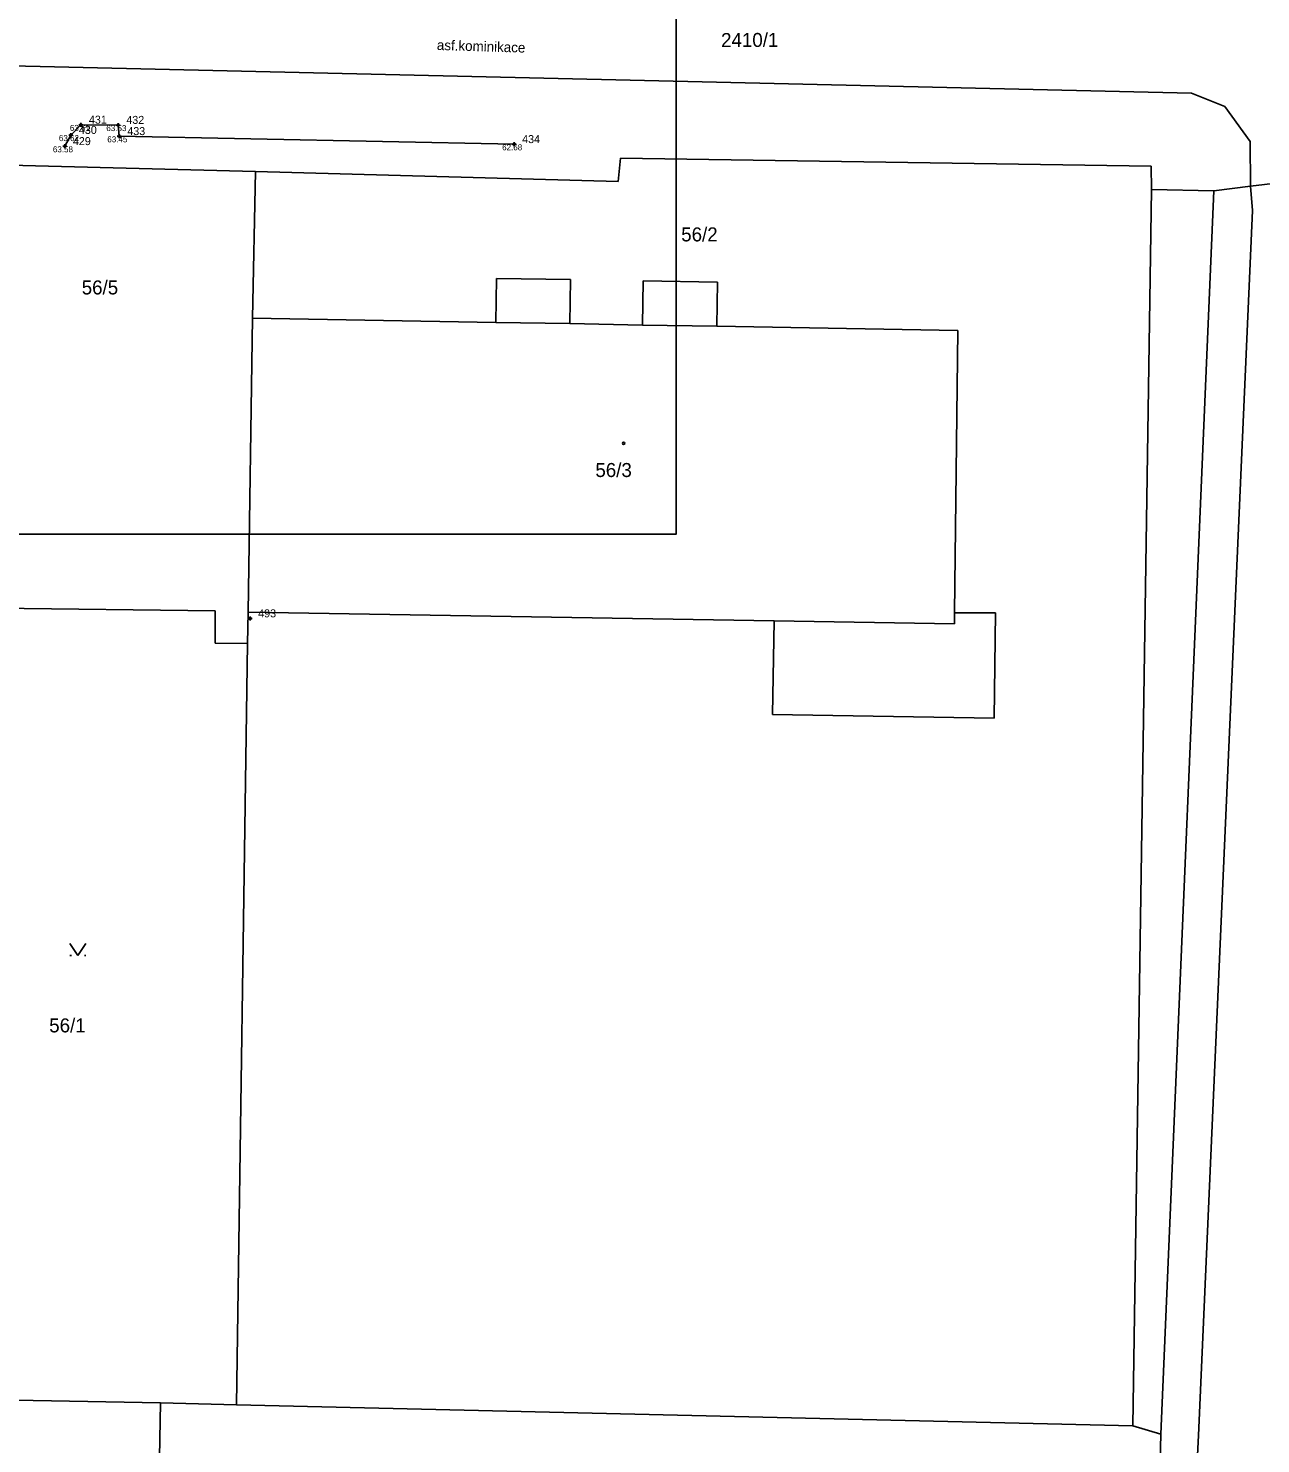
# Model space of a CAD drawing. Extents: x -454285 to -453563, y -1108687 to -1108249.
# Drawn here: x -453822.5 to -453760.9, y -1108547.2 to -1108476.5 of the extents above; entities that cross this region are included whole.
import ezdxf

# ---------------------------------------------------------------- set-up
doc = ezdxf.new("R2010")
doc.units = 0
for name, color, linetype in [('1', 7, 'Continuous'), ('14', 7, 'Continuous'), ('15', 7, 'Continuous'), ('16', 7, 'Continuous'), ('2', 7, 'Continuous'), ('23', 7, 'Continuous'), ('25', 7, 'Continuous'), ('BODY_T1_2018', 7, 'Continuous'), ('CISLA_T1_2018', 7, 'Continuous'), ('okraj asf.komunikace', 7, 'Continuous'), ('rámy', 7, 'Continuous'), ('T', 7, 'Continuous'), ('VYSKY_T1_2018', 7, 'Continuous')]:
    doc.layers.add(name, color=color, linetype=linetype)

# ---------------------------------------------------------------- blocks, each defined once
blk = doc.blocks.new('Z402')
for start, end in [(0, 180), (180, 0)]:
    blk.add_arc((0, 0), 0.15, start, end)
blk = doc.blocks.new('Z3140')
for p, q in [((-1, 1.5), (0, 0)), ((-1, 0), (-0.8, 0)), ((0, 0), (1, 1.5)), ((0.8, 0), (1, 0))]:
    blk.add_line(p, q)
blk = doc.blocks.new('POINT_DISPLAY')
for p, q in [((-0.1, 0), (0.1, 0)), ((0, -0.1), (0, 0.1))]:
    blk.add_line(p, q)
blk.add_circle((0, 0), 0.05)
blk = doc.blocks.new('t1_2018')
at = {"layer": 'BODY_T1_2018'}
for p in [(-453820.39, -1108481.82), (-453819.89, -1108481.31), (-453818.02, -1108481.32), (-453817.97, -1108481.88), (-453820.69, -1108482.38), (-453798.24, -1108482.28), (-453811.43, -1108505.98)]:
    blk.add_blockref('POINT_DISPLAY', p, dxfattribs=at)
at = {"layer": 'CISLA_T1_2018'}
for s, p in [('431', (-453819.49, -1108481.25)), ('432', (-453817.62, -1108481.26)), ('430', (-453819.99, -1108481.76)), ('433', (-453817.57, -1108481.82)), ('429', (-453820.29, -1108482.32)), ('434', (-453797.84, -1108482.22)), ('493', (-453811.03, -1108505.92))]:
    blk.add_text(s, height=0.4, dxfattribs=at).set_placement(p)
at = {"layer": 'VYSKY_T1_2018'}
for s, p in [('63.61', (-453820.44, -1108481.61)), ('63.53', (-453818.62, -1108481.62)), ('63.58', (-453821.29, -1108482.68)), ('63.62', (-453820.99, -1108482.12)), ('63.45', (-453818.57, -1108482.18)), ('62.68', (-453798.84, -1108482.58))]:
    blk.add_text(s, height=0.3, dxfattribs=at).set_placement(p)

msp = doc.modelspace()

# ---------------------------------------------------------------- linework, layer by layer
at = {"layer": '1'}
for p, q in [((-453793.047, -1108484.141), (-453792.927, -1108482.971)), ((-453792.927, -1108482.971), (-453766.407, -1108483.371)), ((-453811.157, -1108483.631), (-453826.077, -1108483.251)), ((-453811.157, -1108483.631), (-453811.317, -1108490.961)), ((-453811.157, -1108483.631), (-453793.047, -1108484.141)), ((-453766.407, -1108483.371), (-453766.387, -1108484.531)), ((-453766.387, -1108484.531), (-453763.277, -1108484.601)), ((-453765.927, -1108546.741), (-453763.277, -1108484.601)), ((-453763.277, -1108484.601), (-453761.447, -1108484.371)), ((-453761.447, -1108484.371), (-453757.687, -1108483.911)), ((-453799.117, -1108488.981), (-453799.157, -1108491.181)), ((-453799.117, -1108488.981), (-453795.417, -1108489.041)), ((-453795.417, -1108489.041), (-453795.457, -1108491.241)), ((-453791.827, -1108491.311), (-453791.797, -1108489.111)), ((-453791.797, -1108489.111), (-453788.077, -1108489.171)), ((-453788.077, -1108489.171), (-453788.107, -1108491.371)), ((-453811.537, -1108505.661), (-453811.317, -1108490.961)), ((-453811.317, -1108490.961), (-453799.157, -1108491.181)), ((-453795.457, -1108491.241), (-453791.827, -1108491.311)), ((-453788.107, -1108491.371), (-453776.067, -1108491.581)), ((-453776.237, -1108505.691), (-453776.067, -1108491.581)), ((-453813.187, -1108505.601), (-453826.417, -1108505.431)), ((-453813.187, -1108505.601), (-453813.177, -1108507.211)), ((-453811.537, -1108505.661), (-453811.557, -1108507.221)), ((-453811.537, -1108505.661), (-453785.237, -1108506.091)), ((-453774.187, -1108505.691), (-453776.237, -1108505.691)), ((-453774.247, -1108510.961), (-453774.187, -1108505.691)), ((-453785.237, -1108506.091), (-453785.327, -1108510.781)), ((-453813.177, -1108507.211), (-453811.557, -1108507.221)), ((-453811.557, -1108507.221), (-453812.107, -1108545.271)), ((-453785.327, -1108510.781), (-453774.247, -1108510.961)), ((-453832.427, -1108544.861), (-453815.917, -1108545.181)), ((-453816.177, -1108561.151), (-453815.917, -1108545.181)), ((-453815.917, -1108545.181), (-453812.107, -1108545.271)), ((-453812.107, -1108545.271), (-453767.317, -1108546.321)), ((-453765.927, -1108546.741), (-453767.887, -1108627.791)), ((-453767.317, -1108546.321), (-453765.927, -1108546.741))]:
    msp.add_line(p, q, dxfattribs=at)
at = {"layer": '2'}
for p, q in [((-453827.527, -1108478.261), (-453764.397, -1108479.731)), ((-453764.397, -1108479.731), (-453762.717, -1108480.391)), ((-453762.717, -1108480.391), (-453761.457, -1108482.141)), ((-453761.457, -1108482.141), (-453761.447, -1108484.371)), ((-453766.387, -1108484.531), (-453767.317, -1108546.321)), ((-453761.447, -1108484.371), (-453761.347, -1108485.581)), ((-453761.347, -1108485.581), (-453764.047, -1108546.801)), ((-453799.157, -1108491.181), (-453795.457, -1108491.241)), ((-453791.827, -1108491.311), (-453788.107, -1108491.371)), ((-453776.237, -1108505.691), (-453776.237, -1108506.241)), ((-453785.237, -1108506.091), (-453776.237, -1108506.241)), ((-453764.107, -1108548.121), (-453764.047, -1108546.801))]:
    msp.add_line(p, q, dxfattribs=at)
at = {"layer": 'okraj asf.komunikace'}
msp.add_lwpolyline([(-453820.69, -1108482.38), (-453820.39, -1108481.82), (-453819.89, -1108481.31), (-453818.02, -1108481.32), (-453817.97, -1108481.88), (-453798.24, -1108482.28)], dxfattribs=at)
at = {"layer": 'rámy'}
msp.add_lwpolyline([(-453889.309, -1108441.707), (-453790.141, -1108441.707), (-453790.141, -1108501.759), (-453889.309, -1108501.759)], close=True, dxfattribs=at)

# ---------------------------------------------------------------- block references
msp.add_blockref('t1_2018', (0, 0))
at = {"layer": '23', "xscale": 0.4, "yscale": 0.4000000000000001}
msp.add_blockref('Z3140', (-453820.037, -1108522.821), dxfattribs=at)
at = {"layer": '25', "xscale": 0.4, "yscale": 0.4000000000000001}
msp.add_blockref('Z402', (-453792.767, -1108497.221), dxfattribs=at)

# ---------------------------------------------------------------- texts
at = {"layer": '14'}
for s, p in [('56/2', (-453789.89, -1108487.132)), ('56/5', (-453819.85, -1108489.783)), ('56/1', (-453821.473, -1108526.661))]:
    msp.add_text(s, height=0.7, dxfattribs=at).set_placement(p)
at = {"layer": '15'}
msp.add_text('56/3', height=0.7, dxfattribs=at).set_placement((-453794.18, -1108498.907))
at = {"layer": '16'}
msp.add_text('2410/1', height=0.7, rotation=0.1968, dxfattribs=at).set_placement((-453787.897, -1108477.421))
at = {"layer": 'T'}
msp.add_text('asf.kominikace', height=0.5, rotation=358.20729, dxfattribs=at).set_placement((-453802.107, -1108477.563))

doc.saveas('drawing.dxf')
